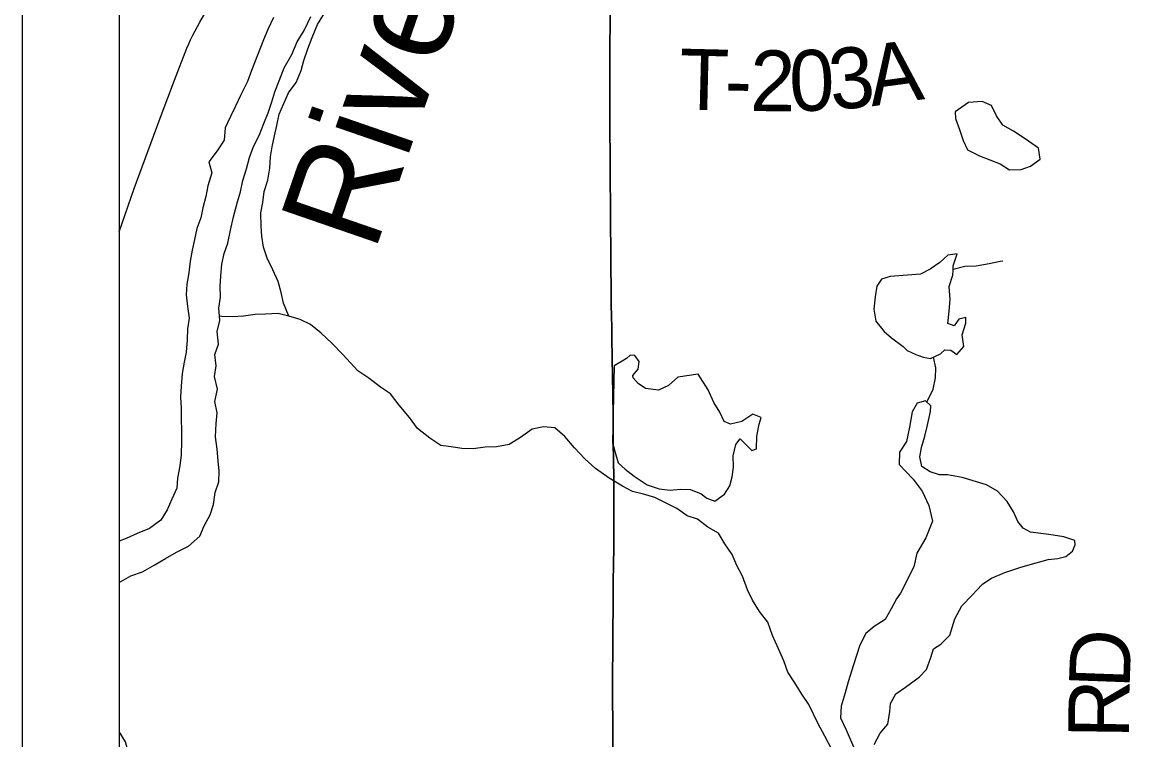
# Model space of a CAD drawing. Extents: x 0 to 34, y 0 to 22.
# Drawn here: x 12.556 to 13.592, y 14.297 to 14.967 of the extents above; entities that cross this region are included whole.
import ezdxf

# ---------------------------------------------------------------- set-up
doc = ezdxf.new("R2010")
doc.units = 0
for name, color, linetype in [('GM_X_Corporation', 7, 'Continuous'), ('GM_X_County_Road', 7, 'Continuous'), ('GM_X_County_Road_Text', 7, 'Continuous'), ('GM_X_Major_River', 7, 'Continuous'), ('GM_X_Major_River_Text', 7, 'Continuous'), ('GM_X_Minor_Lake', 7, 'Continuous'), ('GM_X_Minor_River', 7, 'Continuous'), ('GM_X_Township_Road', 7, 'Continuous'), ('GM_X_Township_Road_Text', 7, 'Continuous'), ('SH_Data', 7, 'Continuous')]:
    doc.layers.add(name, color=color, linetype=linetype)

msp = doc.modelspace()

# ---------------------------------------------------------------- linework, layer by layer
at = {"layer": 'GM_X_Corporation'}
for points in [[(12.6467, 16.7214), (12.6467, 12.6578)], [(12.6467, 16.7214), (12.6467, 12.6578)], [(13.1082, 14.2879), (13.1081, 14.3017), (13.108, 14.3112), (13.1079, 14.3369), (13.1078, 14.3564), (13.108, 14.3825), (13.1082, 14.4055), (13.1083, 14.4149), (13.1084, 14.4323), (13.1085, 14.4476), (13.1086, 14.4575), (13.1089, 14.4791), (13.1091, 14.5009), (13.109, 14.5144), (13.1089, 14.5382), (13.1086, 14.5622), (13.1085, 14.5702), (13.1084, 14.5897), (13.1084, 14.6038), (13.1082, 14.6151), (13.1081, 14.6225), (13.1079, 14.6336), (13.1074, 14.6558), (13.1071, 14.6694), (13.107, 14.6818), (13.1066, 14.7032), (13.1064, 14.7195), (13.1062, 14.7375), (13.1061, 14.761), (13.106, 14.7717), (13.1055, 14.8444), (13.1054, 14.864), (13.1053, 14.8827), (13.1053, 14.928), (13.1054, 14.9458), (13.1055, 14.9657), (13.1056, 14.9746)], [(13.1082, 14.2879), (13.1081, 14.3017), (13.108, 14.3112), (13.1079, 14.3369), (13.1078, 14.3564), (13.108, 14.3825), (13.1082, 14.4055), (13.1083, 14.4149), (13.1084, 14.4323), (13.1085, 14.4476), (13.1086, 14.4575), (13.1089, 14.4791), (13.1091, 14.5009), (13.109, 14.5144), (13.1089, 14.5382), (13.1086, 14.5622), (13.1085, 14.5702), (13.1084, 14.5897), (13.1084, 14.6038), (13.1082, 14.6151), (13.1081, 14.6225), (13.1079, 14.6336), (13.1074, 14.6558), (13.1071, 14.6694), (13.107, 14.6818), (13.1066, 14.7032), (13.1064, 14.7195), (13.1062, 14.7375), (13.1061, 14.761), (13.106, 14.7717), (13.1055, 14.8444), (13.1054, 14.864), (13.1053, 14.8827), (13.1053, 14.928), (13.1054, 14.9458), (13.1055, 14.9657), (13.1056, 14.9746)], [(13.1056, 14.9746), (13.1055, 14.9657), (13.1054, 14.9458), (13.1053, 14.928), (13.1053, 14.8827), (13.1054, 14.864), (13.1055, 14.8444), (13.106, 14.7717), (13.1061, 14.761), (13.1062, 14.7375), (13.1064, 14.7195), (13.1066, 14.7032), (13.107, 14.6818), (13.1071, 14.6694), (13.1074, 14.6558), (13.1079, 14.6336), (13.1081, 14.6225), (13.1082, 14.6151), (13.1084, 14.6038), (13.1084, 14.5897), (13.1085, 14.5702), (13.1086, 14.5622), (13.1089, 14.5382), (13.109, 14.5144), (13.1091, 14.5009), (13.1089, 14.4791), (13.1086, 14.4575), (13.1085, 14.4476), (13.1084, 14.4323), (13.1083, 14.4149), (13.1082, 14.4055), (13.108, 14.3825), (13.1078, 14.3564), (13.1079, 14.3369), (13.108, 14.3112), (13.1081, 14.3017), (13.1082, 14.2879)]]:
    msp.add_lwpolyline(points, dxfattribs=at)
at = {"layer": 'GM_X_County_Road'}
msp.add_lwpolyline([(12.6467, 14.7714), (12.6608, 14.8118), (12.6787, 14.8608), (12.6858, 14.8801), (12.6984, 14.9131), (12.71, 14.9428), (12.7117, 14.947), (12.7133, 14.9507), (12.7156, 14.9551), (12.7176, 14.959), (12.7219, 14.967), (12.7356, 14.991), (12.753, 15.0197), (12.7751, 15.055), (12.794, 15.0864), (12.806, 15.106), (12.8236, 15.1324), (12.8293, 15.1408)], dxfattribs=at)
at = {"layer": 'GM_X_Major_River'}
for points in [[(12.6467, 14.4438), (12.6574, 14.4499), (12.6683, 14.4538), (12.6792, 14.46), (12.6898, 14.4662), (12.7003, 14.472), (12.7116, 14.4778), (12.7221, 14.4871), (12.7262, 14.4966), (12.7317, 14.5069), (12.7347, 14.5165), (12.7364, 14.5279), (12.7397, 14.5378), (12.74, 14.5477), (12.7391, 14.5575), (12.7382, 14.5682), (12.7366, 14.5799), (12.7372, 14.5921), (12.7382, 14.6023), (12.7362, 14.6129), (12.7384, 14.6244), (12.7356, 14.6361), (12.7374, 14.646), (12.7361, 14.6566), (12.7394, 14.6665), (12.7381, 14.6783), (12.7407, 14.6886), (12.7398, 14.7), (12.7412, 14.7102), (12.7411, 14.7205), (12.7417, 14.73), (12.7427, 14.741), (12.7449, 14.7509), (12.7482, 14.7608), (12.7507, 14.773), (12.7536, 14.7852), (12.7572, 14.7993), (12.7602, 14.8088), (12.7623, 14.8191), (12.7656, 14.8301), (12.7685, 14.8408), (12.7722, 14.8511), (12.7774, 14.8614), (12.7818, 14.8725), (12.7859, 14.8824), (12.7892, 14.8927), (12.7921, 14.9022), (12.7961, 14.9122), (12.8009, 14.9244), (12.808, 14.937), (12.8131, 14.9488), (12.8195, 14.9595), (12.8258, 14.9725)], [(12.7908, 14.9714), (12.7856, 14.9604), (12.7815, 14.9505), (12.7704, 14.9219), (12.7667, 14.9117), (12.76, 14.8987), (12.7555, 14.8888), (12.7507, 14.8789), (12.7458, 14.8683), (12.7448, 14.8569), (12.7381, 14.847)], [(12.7381, 14.847), (12.7306, 14.8367), (12.7333, 14.8265), (12.7296, 14.8143), (12.7278, 14.8044), (12.7249, 14.7938), (12.723, 14.7843), (12.7193, 14.7744), (12.7171, 14.7641), (12.7149, 14.7542), (12.7131, 14.744), (12.7117, 14.733), (12.7099, 14.7223), (12.7092, 14.7125), (12.7104, 14.7015), (12.712, 14.6905), (12.7106, 14.6806), (12.7103, 14.6704), (12.7092, 14.659), (12.7074, 14.6495), (12.7056, 14.6389), (12.7046, 14.6271), (12.7039, 14.6168), (12.7047, 14.6066), (12.705, 14.5755), (12.7047, 14.563), (12.7032, 14.5527), (12.7011, 14.5413), (12.7004, 14.5319), (12.6959, 14.5216), (12.6915, 14.5117), (12.6855, 14.5018), (12.6749, 14.4941), (12.6636, 14.4895), (12.6531, 14.4848), (12.6467, 14.4824)], [(12.7207, 14.1339), (12.7139, 14.1527), (12.71, 14.1625), (12.7009, 14.173), (12.6951, 14.1829), (12.6905, 14.1931), (12.687, 14.2033), (12.6869, 14.2128), (12.685, 14.2226), (12.6807, 14.2324), (12.6757, 14.2438), (12.6696, 14.2536), (12.6627, 14.2645), (12.6588, 14.2744), (12.6554, 14.2846), (12.6526, 14.2948), (12.6467, 14.3045)]]:
    msp.add_lwpolyline(points, dxfattribs=at)
at = {"layer": 'GM_X_Minor_Lake'}
for p, q in [((13.4508, 14.8422), (13.4701, 14.8348)), ((13.3956, 14.7318), (13.3672, 14.7297)), ((13.1094, 14.6462), (13.1077, 14.5741)), ((13.3893, 14.4585), (13.3771, 14.4339))]:
    msp.add_line(p, q, dxfattribs=at)
for points in [[(13.4701, 14.8348), (13.4789, 14.8292), (13.4898, 14.8296), (13.4985, 14.8327), (13.5075, 14.8393), (13.506, 14.8495), (13.4934, 14.8581), (13.4827, 14.8652), (13.4725, 14.8709), (13.4667, 14.8795), (13.4621, 14.8894), (13.4534, 14.8931), (13.4405, 14.8922), (13.4281, 14.8834), (13.4285, 14.8773), (13.432, 14.8668), (13.4355, 14.8565), (13.4397, 14.8478), (13.4508, 14.8422)], [(13.3672, 14.7297), (13.3593, 14.727), (13.3548, 14.7205), (13.3534, 14.7106), (13.3519, 14.6989), (13.3539, 14.6879), (13.3616, 14.6781), (13.3684, 14.6724), (13.3795, 14.6642), (13.3833, 14.6604), (13.3912, 14.6567), (13.3981, 14.6541), (13.4049, 14.653), (13.4143, 14.6572), (13.4185, 14.6611), (13.4241, 14.6607), (13.4295, 14.6566), (13.4362, 14.6642), (13.4346, 14.6752), (13.438, 14.6859), (13.4379, 14.6912), (13.4315, 14.6896), (13.427, 14.6835), (13.4213, 14.6857), (13.4223, 14.6971), (13.4234, 14.7081), (13.4225, 14.7203), (13.4259, 14.7309), (13.4262, 14.7351), (13.4262, 14.7396), (13.4299, 14.7507), (13.4212, 14.7495), (13.4137, 14.7426), (13.4046, 14.7364), (13.3956, 14.7318)], [(13.1077, 14.5741), (13.1108, 14.5631), (13.1131, 14.5555), (13.1196, 14.5495), (13.1279, 14.5431), (13.1401, 14.5349), (13.1515, 14.5312), (13.1617, 14.5301), (13.1712, 14.531), (13.1807, 14.5307), (13.1905, 14.5266), (13.1959, 14.5224), (13.2034, 14.5198), (13.2125, 14.5263), (13.2173, 14.534), (13.2195, 14.5423), (13.221, 14.5514), (13.2205, 14.5621), (13.2231, 14.5727), (13.2272, 14.578), (13.2322, 14.5728), (13.2379, 14.5671), (13.2424, 14.5687), (13.2427, 14.5804), (13.2449, 14.5915), (13.2467, 14.5979), (13.2388, 14.6009), (13.2286, 14.594), (13.218, 14.5916), (13.212, 14.5942), (13.2081, 14.6029), (13.2024, 14.612), (13.1973, 14.6237), (13.1878, 14.6384), (13.1689, 14.6356), (13.1602, 14.6276), (13.1508, 14.6234), (13.1387, 14.6248), (13.1318, 14.6297), (13.1272, 14.6349), (13.1268, 14.6372), (13.1317, 14.6429), (13.1328, 14.6501), (13.1286, 14.6558), (13.1244, 14.6561), (13.1207, 14.6531), (13.1169, 14.6504), (13.1094, 14.6462)], [(13.3524, 14.2923), (13.358, 14.3029), (13.3651, 14.3113), (13.3669, 14.3231), (13.3676, 14.3307), (13.3725, 14.3398), (13.3815, 14.346), (13.3943, 14.3552), (13.4011, 14.3624), (13.4052, 14.3735), (13.4077, 14.3818), (13.4145, 14.386), (13.4232, 14.3945), (13.4276, 14.4097), (13.4343, 14.4218), (13.4441, 14.4322), (13.4478, 14.436), (13.4538, 14.4425), (13.4621, 14.4479), (13.4746, 14.4529), (13.4893, 14.4579), (13.5036, 14.4622), (13.515, 14.4653), (13.524, 14.4662), (13.5316, 14.4681), (13.5376, 14.4731), (13.5402, 14.4788), (13.5398, 14.483), (13.5296, 14.4863), (13.5155, 14.4885), (13.4985, 14.4906), (13.4917, 14.4944), (13.4867, 14.5008), (13.4825, 14.5098), (13.4767, 14.5193), (13.4675, 14.5291), (13.4573, 14.5351), (13.4345, 14.5417), (13.4209, 14.5443), (13.4133, 14.5442), (13.4046, 14.5472), (13.397, 14.552), (13.395, 14.5611), (13.3965, 14.5699), (13.3998, 14.5805), (13.402, 14.5893), (13.4049, 14.6033), (13.4052, 14.6086), (13.4003, 14.6135), (13.3924, 14.6112), (13.3879, 14.6032), (13.3853, 14.5887), (13.3824, 14.5754), (13.3761, 14.5655), (13.3758, 14.5538), (13.3887, 14.5402), (13.3972, 14.5289), (13.4033, 14.5157), (13.4068, 14.5009), (13.4005, 14.4853), (13.3923, 14.4712), (13.3893, 14.4585)], [(13.3771, 14.4339), (13.3733, 14.4286), (13.3681, 14.4191), (13.3625, 14.4092), (13.3523, 14.4026), (13.3444, 14.3961), (13.3388, 14.3851), (13.3329, 14.3668), (13.3281, 14.3509), (13.3252, 14.3406), (13.3215, 14.3281), (13.3208, 14.3174), (13.3262, 14.3061), (13.3331, 14.2902)]]:
    msp.add_lwpolyline(points, dxfattribs=at)
at = {"layer": 'GM_X_Minor_River'}
for points in [[(12.8051, 14.6924), (12.8001, 14.7045), (12.7981, 14.7147), (12.7954, 14.7249), (12.7904, 14.7359), (12.785, 14.7468), (12.7815, 14.757), (12.7799, 14.7673), (12.7795, 14.7767), (12.779, 14.7889), (12.7808, 14.7988), (12.7823, 14.809), (12.7856, 14.8197), (12.7874, 14.8307), (12.7881, 14.8413), (12.7895, 14.8508), (12.7917, 14.861), (12.7939, 14.8705), (12.7961, 14.8812), (12.805, 14.901), (12.8121, 14.9109), (12.8166, 14.9219), (12.8192, 14.9314), (12.8229, 14.9421), (12.8269, 14.9527), (12.8321, 14.9649), (12.8437, 14.9836)], [(13.4262, 14.7363), (13.4372, 14.7393), (13.4478, 14.7394), (13.4599, 14.7418), (13.4701, 14.7438), (13.4727, 14.7442)], [(13.3127, 14.2878), (13.3062, 14.3002), (13.3, 14.3116), (13.2912, 14.3297), (13.2847, 14.3395), (13.2782, 14.3501), (13.2717, 14.3599), (13.2678, 14.3705), (13.2628, 14.3818), (13.2574, 14.3943), (13.2528, 14.4068), (13.2451, 14.4166), (13.2386, 14.4272), (13.234, 14.437), (13.2293, 14.4495), (13.224, 14.4597), (13.2197, 14.4699), (13.2128, 14.4797), (13.2067, 14.4899), (13.1968, 14.4955), (13.1873, 14.503), (13.1774, 14.506), (13.1679, 14.5127), (13.1474, 14.5232), (13.1368, 14.5261), (13.1265, 14.5287), (13.117, 14.5336), (13.1045, 14.5411), (13.0919, 14.5501), (13.082, 14.5591), (13.0721, 14.5696), (13.0633, 14.5802), (13.0538, 14.5881), (13.0432, 14.5891), (13.0326, 14.5868), (13.0217, 14.5791), (13.0112, 14.5726), (12.9994, 14.5706), (12.9888, 14.5701), (12.9775, 14.5685), (12.9669, 14.5688), (12.9571, 14.5706), (12.9472, 14.5717), (12.9369, 14.5785), (12.9255, 14.5875), (12.9179, 14.598), (12.9083, 14.6093), (12.9003, 14.6199), (12.8908, 14.6263), (12.8801, 14.6345), (12.8698, 14.6413), (12.8557, 14.6567), (12.8454, 14.6673), (12.8355, 14.6767), (12.8256, 14.6846), (12.8157, 14.6894), (12.8051, 14.6924), (12.7952, 14.6949), (12.7835, 14.6945), (12.7737, 14.694), (12.7627, 14.6924), (12.7525, 14.6919), (12.7427, 14.6923), (12.7404, 14.6925)], [(13.4016, 14.6123), (13.4074, 14.6242), (13.4096, 14.6348), (13.4099, 14.6443), (13.4077, 14.6543)]]:
    msp.add_lwpolyline(points, dxfattribs=at)
at = {"layer": 'GM_X_Township_Road'}
msp.add_lwpolyline([(13.1084, 14.2874), (13.1083, 14.3012), (13.1082, 14.3106), (13.1081, 14.3364), (13.108, 14.3558), (13.1082, 14.3819), (13.1084, 14.405), (13.1085, 14.4143), (13.1086, 14.4318), (13.1087, 14.4471), (13.1088, 14.4569), (13.1091, 14.4785), (13.1093, 14.5004), (13.1092, 14.5139), (13.1091, 14.5377), (13.1088, 14.5617), (13.1087, 14.5697), (13.1086, 14.5892), (13.1086, 14.6033), (13.1084, 14.6146), (13.1083, 14.622), (13.1081, 14.633), (13.1076, 14.6552), (13.1073, 14.6689), (13.1072, 14.6812), (13.1068, 14.7026), (13.1066, 14.7189), (13.1064, 14.737), (13.1063, 14.7604), (13.1062, 14.7711), (13.1057, 14.8439), (13.1056, 14.8634), (13.1056, 14.8821), (13.1055, 14.9274), (13.1056, 14.9453), (13.1057, 14.9652), (13.1058, 14.9741)], dxfattribs=at)
at = {"layer": 'SH_Data'}
msp.add_line((12.556, 16.8098), (12.556, 9.8098), dxfattribs=at)

# ---------------------------------------------------------------- texts
at = {"layer": 'GM_X_County_Road_Text'}
for s, rotation, p in [('D', 87.8976, (13.591, 14.3442)), ('R', 89.2467, (13.5904, 14.2979))]:
    msp.add_text(s, height=0.0568, rotation=rotation, dxfattribs=at).set_placement(p)
at = {"layer": 'GM_X_Major_River_Text'}
msp.add_text('River', height=0.09476, rotation=70.9752, dxfattribs=at).set_placement((12.8851, 14.7509))
at = {"layer": 'GM_X_Township_Road_Text'}
for s, rotation, p in [('3', 5.2974, (13.3126, 14.885)), ('A', 7.7525, (13.3501, 14.8885)), ('T', 358.6156, (13.1696, 14.8857)), ('2', 359.2833, (13.2361, 14.8842)), ('0', 1.6589, (13.2737, 14.8838)), ('-', 358.7517, (13.2122, 14.8847))]:
    msp.add_text(s, height=0.0568, rotation=rotation, dxfattribs=at).set_placement(p)

doc.saveas('drawing.dxf')
